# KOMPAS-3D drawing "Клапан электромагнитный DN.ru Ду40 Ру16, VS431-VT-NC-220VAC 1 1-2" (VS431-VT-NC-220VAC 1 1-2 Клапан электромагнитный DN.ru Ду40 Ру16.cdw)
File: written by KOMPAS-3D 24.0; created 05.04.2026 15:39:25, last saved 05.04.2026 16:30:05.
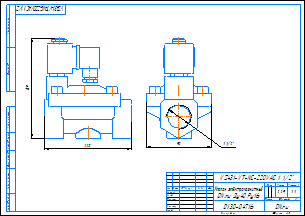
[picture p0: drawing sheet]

Document properties: c3d_UniqueCompID: ef56311e-7521-43dc-8291-0e6108b3d81d; Автор: artio; Класс точности: c; Знак неуказанной шероховатости: Шероховатость не задана; Рассекать на разрезах: Да; c3d_UniqueCompID: ef56311e-7521-43dc-8291-0e6108b3d81d; Автор: artio; Класс точности: c; Знак неуказанной шероховатости: Шероховатость не задана; Рассекать на разрезах: Да; c3d_UniqueCompID: ef56311e-7521-43dc-8291-0e6108b3d81d; Автор: artio; Класс точности: c; Знак неуказанной шероховатости: Шероховатость не задана; Рассекать на разрезах: Да; c3d_UniqueCompID: ef56311e-7521-43dc-8291-0e6108b3d81d; Автор: artio; Класс точности: c; Знак неуказанной шероховатости: Шероховатость не задана; Рассекать на разрезах: Да; Автор: artio; Форматы листов документа: A3; Полное имя файла: VS431-VT-NC-220VAC 1 1-2 Клапан электромагнитный DN.ru Ду40 Ру16.m3d; Масса: 2.285; Наименование: Клапан электромагнитный DN.ru Ду40 Ру16; Количество листов документа: 1; Примечание: D130-04716

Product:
- Body: Тело 1  | qty 1
    Масса: 3.859459
- Part/product: Клапан электромагнитный DN.ru Ду40 Ру16  | designation VS431-VT-NC-220VAC 1 1-2
    Масса: 2.285
    Раздел спецификации: Прочие изделия
    Примечание: D130-04716
    additional columns: ef56311e-7521-43dc-8291-0e6108b3d81d; artio; c; Шероховатость не задана; Да

Views: Вид 1, Спереди
Referenced files in C:\Users\artio\OneDrive\Рабочий стол\Клапан электромагнитный DN.ru\VS431\VS431-ET-NC\: VS431-ET-NC-220VAC 3-4 Клапан электромагнитный DN.ru Ду20 Ру16.m3d, VS431-ET-NC-220VAC 3-4 Клапан электромагнитный DN.ru Ду20 Ру16.cdw
Referenced files in C:\Users\artio\OneDrive\Рабочий стол\Клапан электромагнитный DN.ru\VS431\VS431-VT-NC\: VS431-VT-NC-220VAC 1 1-2 Клапан электромагнитный DN.ru Ду40 Ру16.m3d
Referenced files in C:\Users\artio\OneDrive\Рабочий стол\Клапан электромагнитный DN.ru\VS431\VS431-VT-NC\VS431-VT-NC-220VAC\Ду40\: VS431-VT-NC-220VAC 1 1-2 Клапан электромагнитный DN.ru Ду40 Ру16.m3d
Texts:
  VS431-VT-NC-220VAC 1 1-2
  Клапан электромагнитный
  DN.ru Ду40 Ру16
  VS431-VT-NC-220VAC 1 1/2"
  VS431-VT-NC-220VAC 1 1/2"-
  Клапан электромагнитный DN.ru Ду40 Ру16
  VS431-VT-NC-220VAC 1 1-2 Клапан электромагнитный DN.ru Ду40 Ру16
Dimensions and other numbers on the sheet: 0; 3; 2; 4; 90; 1 1/2"; 1:1; 1; 2,29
